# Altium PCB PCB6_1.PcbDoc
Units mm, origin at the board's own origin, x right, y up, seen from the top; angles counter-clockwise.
Board outline 13 x 20 mm, 2 copper layers (Top Layer, Bottom Layer); 1 components, 0 nets, 8 pads, 0 vias.
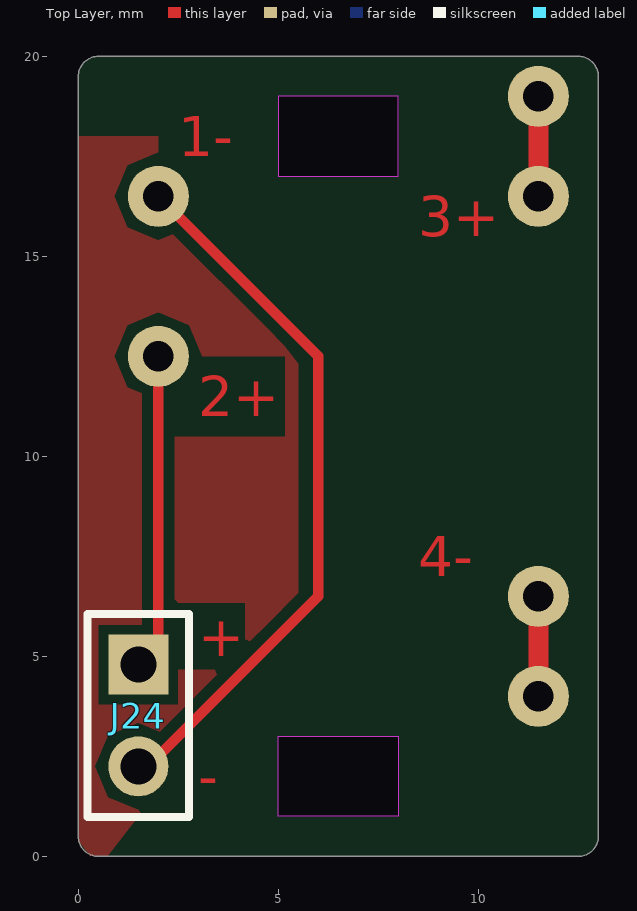
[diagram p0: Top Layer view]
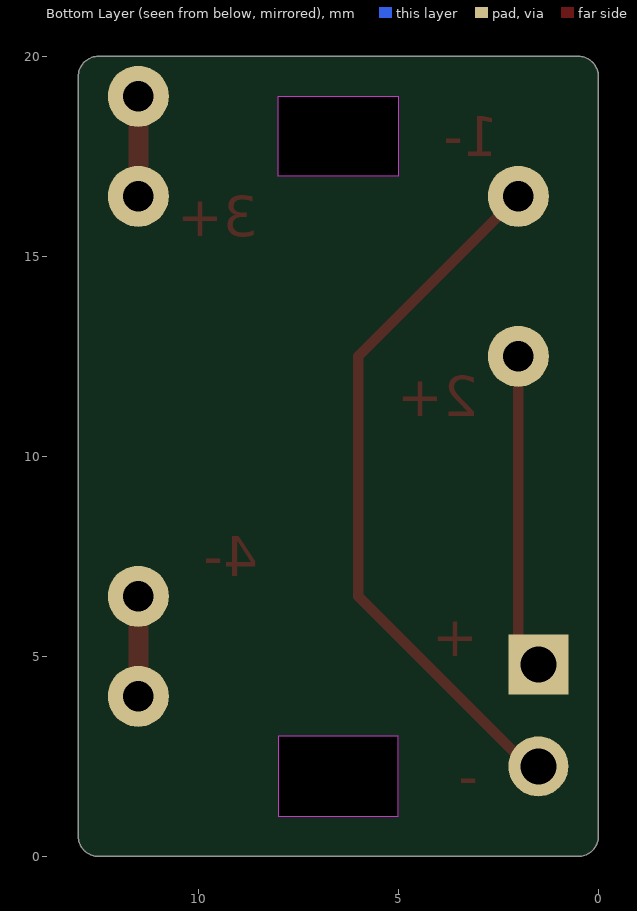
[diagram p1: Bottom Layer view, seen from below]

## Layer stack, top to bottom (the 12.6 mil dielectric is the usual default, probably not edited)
Top Solder: solder mask 0.0102, Solder Resist, Dk 3.5
Top Layer: signal copper 0.0356
Dielectric 1: dielectric 0.32, FR-4, Dk 4.8
Bottom Layer: signal copper 0.0356
Bottom Solder: solder mask 0.0102, Solder Resist, Dk 3.5

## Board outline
0,0.5 ccw(c0.5,0.5) 0.5,0 12.5,0 ccw(c12.5,0.5) 13,0.5 13,19.5 ccw(c12.5,19.5) 12.5,20 0.5,20 ccw(c0.5,19.5) 0,19.5
cut-out: 5,3 8,3 8,1 5,1
cut-out: 8,17 8,19 5,19 5,17

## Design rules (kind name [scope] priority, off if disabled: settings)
Clearance [All] p1: gap=0.254
PolygonConnect [All] p1: connectstyle=Relief reliefconductorwidth=0.254 reliefentries=4 polygonreliefangle="90 Angle" airgapwidth=0.254
RoutingVias [All] p1: holewidth=0.711 width=1.27 viastyle="Through Hole" minholewidth=0.711 minwidth=1.27 maxholewidth=0.711 maxwidth=1.27
SolderMaskExpansion [All] p1: expansion=0.102
Width [All] p1: maxlimit=0.254 minlimit=0.254 preferedwidth=0.254
29 further rules are at their usual default settings.

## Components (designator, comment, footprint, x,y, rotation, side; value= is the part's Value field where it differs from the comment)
J24 "Comment" HDR2X1_A 1.5,4.79 r270 top

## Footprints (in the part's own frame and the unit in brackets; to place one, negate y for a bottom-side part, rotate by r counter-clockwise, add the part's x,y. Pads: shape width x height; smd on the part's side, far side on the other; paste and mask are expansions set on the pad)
HDR2X1_A [mm] "Connector; Header; 2 Position"
  rect 1.5x1.5 hole 0.9: 1(0,0)
  round 1.5 hole 0.9: 2(2.54,0)
  silkscreen extent -1.27,-1.27 3.81,1.27

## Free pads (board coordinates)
  round 1.524 hole 0.762: 4(2,12.5) 5(2,16.5) 6(11.5,4) 6(11.5,16.5) 6(11.5,19) 7(11.5,6.5)

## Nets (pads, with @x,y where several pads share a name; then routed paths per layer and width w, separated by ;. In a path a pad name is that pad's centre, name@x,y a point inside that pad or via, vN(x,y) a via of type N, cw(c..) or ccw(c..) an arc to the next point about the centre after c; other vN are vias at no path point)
pads on no net: J24.1 J24.2
copper on no net: | length 30.8
  Top Layer w0.254: 1.5,2.25 1.75,2.25 5,5.5 6,6.5 6,8.5 6,10.5 6,12.5 5,13.5 2,16.5 ; 1.5,4.79 2,5.29 2,12.5
  Top Layer w0.5: 11.5,4 11.5,6.5 ; 11.5,16.5 11.5,19

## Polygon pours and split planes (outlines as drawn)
no net on Top Layer "Top Layer-No Net" (solid, pour order 24): 0,18 2.567,18 2.567,16.105 5.133,12.789 5.5,12.316 5.5,6.158 0.733,0 0.726,0.009 0.295,0.009 0.007,0.381 0,0.39 0,18

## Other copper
Top Layer:
  text "1-" at 2.5,17.5 h1
  text "3+" at 8.5,15.5 h1
  text "2+" at 3,11 h1
  text "4-" at 8.5,7 h1
  text "+" at 3,5 h1
  text "-" at 3,1.5 h1

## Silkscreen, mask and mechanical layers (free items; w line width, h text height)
Mechanical 1:
  lines w0.254: 0,0.5 ccw(c0.5,0.5) 0.5,0 12.5,0 ccw(c12.5,0.5) 13,0.5 13,19.5 ccw(c12.5,19.5) 12.5,20 0.5,20 ccw(c0.5,19.5) 0,19.5 0,0.5 ; 5,1 8,1 8,3 5,3 5,1 ; 5,17 8,17 8,19 5,19 5,17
